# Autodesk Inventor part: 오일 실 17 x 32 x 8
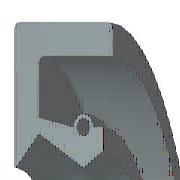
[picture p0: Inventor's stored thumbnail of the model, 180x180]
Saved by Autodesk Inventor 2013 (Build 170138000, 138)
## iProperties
Created: 2012-02
Part Number: 오일 실 17 x 32 x 8
Material: 고무
Description: 샤프트 실 링
Document SubType Name: Modeling
Standard: JIS B 2402
Designer: mdu-01
Standards Organization: JIS
Language: ko-KR
Size Designation: D 17 x 32 x 8
Categories: <MemberInstance><Categories><Category DisplayName="샤프트 부품" InternalName="7f7aeb1f-a693-4053-b835-cee3144e0d98" Mnemonic="SHFT"><Category DisplayName="실링" Intern
Density: 0.93 g/cm^3
Mass: 2.28027 g
Surface Area: 32.1224 cm^2
Volume: 2.45191 cm^3
IsCustomPart: 1
Author: mdu-01
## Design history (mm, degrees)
revolve "본체" stored, may be unused: angle "d17" = 90 deg
revolve "스프링1" stored, may be unused: angle "d18" = 90 deg
body "Solid1"
sketch "스케치1"
  geometry: L1 (0, 16)-(8, 16); L2 (8, 14.25)-(1.75, 14.25); L3 (1.75, 10.25)-(4.9, 8.5); L4 (4.9, 8.5)-(0, 8.5); L5 (0, 0)-(9.586, 0) reference; L6 (4.9, 8.5)-(6.3, 9.375); L7 (0, 18)-(0, -3) reference; L8 (-1.941, 0)-(11.507, 0) reference; L9 (4.2, 10.6)-(1.75, 11.21); L10 (1.75, 11.21)-(1.75, 14.25); L11 (0, 16)-(0, 8.588); L12 (4.9, 8.5)-(0, 8.5); L13 (1.75, 10.25)-(0.152, 8.528); L14 (8, 16)-(8, 14.25); L15 (5.6, 10.6)-(6.3, 10.6); L16 (6.3, 10.6)-(6.3, 9.375); C1 r 0.455 at (4.9, 10.6); A1 r 0.7 centre (4.9, 10.6) between (5.6, 10.6) and (4.2, 10.6); A2 r 0.088 centre (0.088, 8.588) between (0, 8.588) and (0.152, 8.528); 1 further point
  constraints: 28 end point, 5 horizontal alignment, 5 point on line, 4 point on circle, 4 vertical alignment, 3 centre point, 3 tangent, 2 collinear, 2 horizontal, 2 perpendicular, 1 coincident, 1 parallel
  dimensions: "d0" = 32 diameter of L1 L5 (= SD2); "d1" = 1.75 distance of L1.end L2.start (= SD); "d2" = 0.91 diameter of C1 (= SPDI); "d3" = 1.4 diameter of A1 (= SPDA); "d4" = 17 diameter of L3.end L5 (= NND); "d5" = 20.5 diameter of L3.start L5 (= TKDM); "d7" = 22.42 diameter of L9.end L5 (= TKDM + 0.24 x SWDT); "d8" = 1.75 distance between parallel lines of L11 L10 (= SD); "d9" = 4.9 distance from line of L11 C1.centre (= SPDST); "d10" = 21.2 diameter of C1.centre L5 (= HLDM); "d11" = 0.0875 radius of A2 (= 0.25 x LAB); "d12" = 6.3 distance between parallel lines of L11 L16 (= SDI); "d13" = 18.75 diameter of L6.end L5 (= ABDM); "d14" = 8 distance from line of L11 L1.end (= SWDT)
fillet "모깎기1" dims "d6" = 0.3 (= RR)
other parameters: "SD2" = 32 [user parameter; used in 1 equation term], "SWDT" = 8 [user parameter; used in 2 equation terms], "RR" = 0.3 [user parameter; used in 1 equation term], "SD" = 1.75 [user parameter; used in 2 equation terms], "NND" = 17 [user parameter; used in 1 equation term], "SPDA" = 1.4 [user parameter; used in 1 equation term], "SPDI" = 0.91 [user parameter; used in 1 equation term], "TKDM" = 20.5 [user parameter; used in 2 equation terms], "HLDM" = 21.2 [user parameter; used in 1 equation term], "ABDM" = 18.75 [user parameter; used in 1 equation term], "SDI" = 6.3 [user parameter; used in 1 equation term], "SPDST" = 4.9 [user parameter; used in 1 equation term], "LAB" = 0.35 [user parameter; used in 1 equation term], "d15" = 0, "d16" = 0, "d19" = 0
